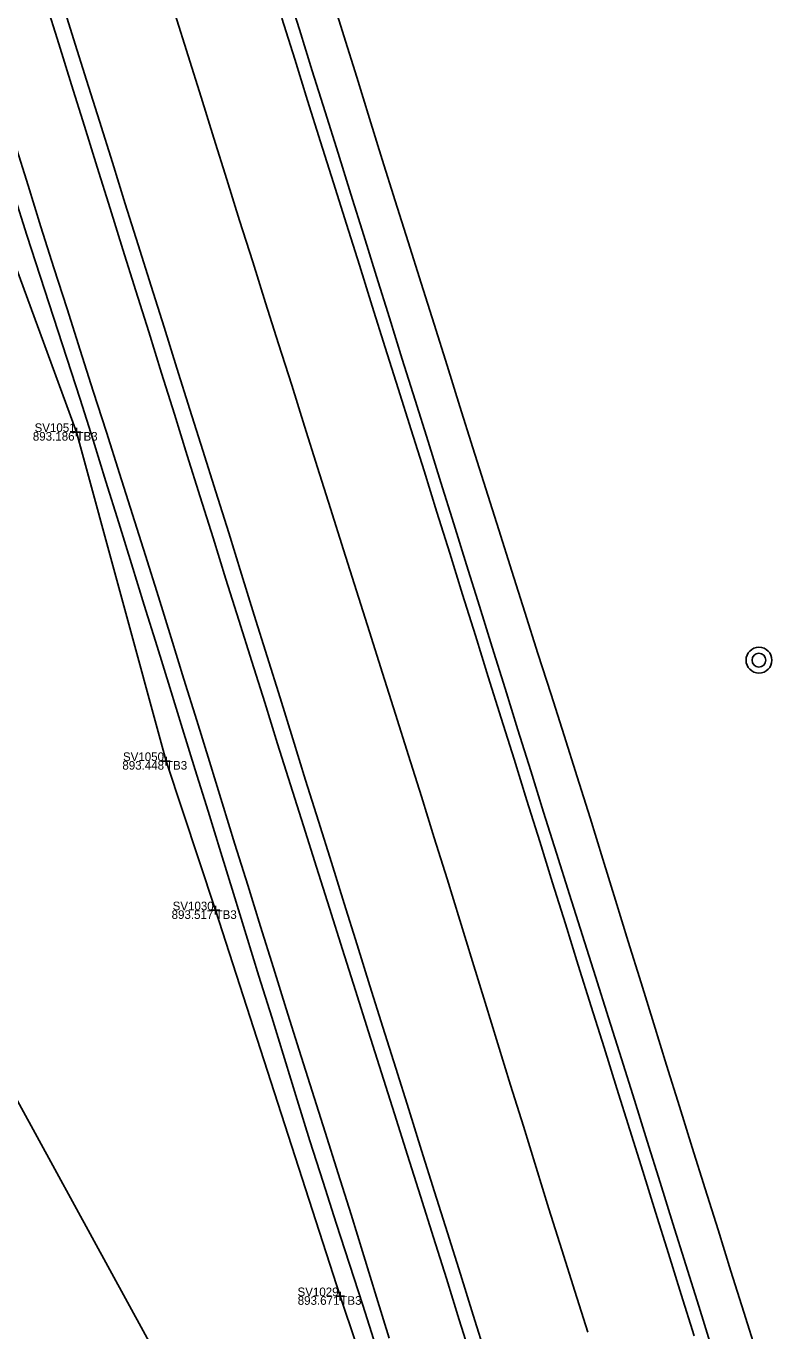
# Model space of a CAD drawing. Extents: x 1918148 to 1919797, y 624701 to 627089.
# Drawn here: x 1919238.3 to 1919324.7, y 625555 to 625706.2 of the extents above; entities that cross this region are included whole.
import ezdxf

# ---------------------------------------------------------------- set-up
doc = ezdxf.new("R2010")
doc.units = 0
for name, color, linetype in [('DR_X_Ditch', 7, 'Continuous'), ('DT_X_Terrain_Boundary', 7, 'Continuous'), ('PM_X_Edge_Line', 7, 'Continuous'), ('PM_X_Lane_Line', 7, 'Continuous'), ('PV_X_EOP', 7, 'Continuous'), ('PV_X_Shoulder_Aggregate', 7, 'Continuous'), ('PV_X_Shoulder_Rumble_Strip', 7, 'Continuous'), ('SV_X_Mon_Cells_Found', 7, 'Continuous'), ('SV_X_Shot_Marker', 7, 'Continuous'), ('SV_X_Text_Comment', 7, 'Continuous'), ('SV_X_Text_Elevation', 7, 'Continuous'), ('SV_X_Text_Name', 7, 'Continuous'), ('SV_X_Top_of_Bank', 7, 'Continuous')]:
    doc.layers.add(name, color=color, linetype=linetype)

msp = doc.modelspace()

# ---------------------------------------------------------------- linework, layer by layer
at = {"layer": 'DR_X_Ditch'}
msp.add_lwpolyline([(1919294.9, 625444.11), (1919278.12, 625494.14), (1919254.13, 625550.83), (1919231.31, 625592.46), (1919223.61, 625606.59), (1919220.8, 625619.65), (1919215.15, 625628.65)], dxfattribs=at)
at = {"layer": 'DT_X_Terrain_Boundary'}
msp.add_lwpolyline([(1919322.98, 625552.38), (1919321.48, 625557.15), (1919319.98, 625561.92), (1919318.49, 625566.69), (1919316.99, 625571.46), (1919315.49, 625576.23), (1919314.01, 625581.01), (1919312.53, 625585.79), (1919311.05, 625590.56), (1919309.57, 625595.34), (1919308.09, 625600.11), (1919306.61, 625604.89), (1919305.13, 625609.67), (1919303.65, 625614.44), (1919302.16, 625619.21), (1919300.64, 625623.98), (1919299.13, 625628.75), (1919297.62, 625633.51), (1919296.11, 625638.28), (1919294.6, 625643.04), (1919293.08, 625647.81), (1919291.57, 625652.58), (1919290.07, 625657.34), (1919288.57, 625662.11), (1919287.07, 625666.88), (1919285.57, 625671.65), (1919284.07, 625676.42), (1919282.57, 625681.19), (1919281.07, 625685.96), (1919279.57, 625690.73), (1919278.08, 625695.5), (1919276.6, 625700.28), (1919275.12, 625705.06), (1919273.64, 625709.83)], dxfattribs=at)
at = {"layer": 'PM_X_Edge_Line'}
for points in [[(1919242.28, 625709.48), (1919243.78, 625704.71), (1919245.27, 625699.94), (1919246.77, 625695.17), (1919248.27, 625690.4), (1919249.76, 625685.62), (1919251.26, 625680.85), (1919252.76, 625676.08), (1919254.26, 625671.31), (1919255.76, 625666.54), (1919257.26, 625661.77), (1919258.76, 625657.01), (1919260.26, 625652.24), (1919261.76, 625647.47), (1919263.24, 625642.69), (1919264.73, 625637.92), (1919266.22, 625633.14), (1919267.71, 625628.37), (1919269.19, 625623.6), (1919270.68, 625618.82), (1919272.17, 625614.05), (1919273.66, 625609.28), (1919275.15, 625604.5), (1919276.65, 625599.73), (1919278.14, 625594.96), (1919279.64, 625590.19), (1919281.14, 625585.42), (1919282.63, 625580.65), (1919284.13, 625575.88), (1919285.63, 625571.11), (1919287.12, 625566.34), (1919288.62, 625561.57), (1919290.11, 625556.8), (1919291.6, 625552.02)], [(1919267.92, 625707.12), (1919269.42, 625702.35), (1919270.91, 625697.57), (1919272.41, 625692.8), (1919273.91, 625688.03), (1919275.41, 625683.26), (1919276.91, 625678.5), (1919278.41, 625673.73), (1919279.91, 625668.96), (1919281.41, 625664.19), (1919282.91, 625659.42), (1919284.42, 625654.65), (1919285.91, 625649.88), (1919287.39, 625645.1), (1919288.88, 625640.33), (1919290.37, 625635.56), (1919291.86, 625630.78), (1919293.35, 625626.01), (1919294.84, 625621.24), (1919296.32, 625616.46), (1919297.82, 625611.69), (1919299.31, 625606.92), (1919300.8, 625602.15), (1919302.29, 625597.37), (1919303.79, 625592.6), (1919305.28, 625587.83), (1919306.77, 625583.06), (1919308.27, 625578.29), (1919309.76, 625573.51), (1919311.25, 625568.74), (1919312.74, 625563.97), (1919314.22, 625559.2), (1919315.71, 625554.42)]]:
    msp.add_lwpolyline(points, dxfattribs=at)
at = {"layer": 'PM_X_Lane_Line'}
msp.add_lwpolyline([(1919255.57, 625707.53), (1919257.06, 625702.75), (1919258.55, 625697.98), (1919260.04, 625693.21), (1919261.53, 625688.44), (1919263.03, 625683.67), (1919264.54, 625678.9), (1919266.04, 625674.13), (1919267.55, 625669.36), (1919269.06, 625664.6), (1919270.56, 625659.83), (1919272.07, 625655.06), (1919273.57, 625650.29), (1919275.08, 625645.52), (1919276.58, 625640.76), (1919278.09, 625635.99), (1919279.59, 625631.22), (1919281.09, 625626.45), (1919282.6, 625621.68), (1919284.1, 625616.91), (1919285.6, 625612.14), (1919287.08, 625607.37), (1919288.56, 625602.59), (1919290.03, 625597.81), (1919291.5, 625593.03), (1919292.98, 625588.26), (1919294.45, 625583.48), (1919295.92, 625578.7), (1919297.4, 625573.92), (1919298.89, 625569.15), (1919300.39, 625564.38), (1919301.89, 625559.61), (1919303.39, 625554.84)], dxfattribs=at)
at = {"layer": 'PV_X_EOP'}
for points in [[(1919273.64, 625709.83), (1919275.12, 625705.06), (1919276.6, 625700.28), (1919278.08, 625695.5), (1919279.57, 625690.73), (1919281.07, 625685.96), (1919282.57, 625681.19), (1919284.07, 625676.42), (1919285.57, 625671.65), (1919287.07, 625666.88), (1919288.57, 625662.11), (1919290.07, 625657.34), (1919291.57, 625652.58), (1919293.08, 625647.81), (1919294.6, 625643.04), (1919296.11, 625638.28), (1919297.62, 625633.51), (1919299.13, 625628.75), (1919300.64, 625623.98), (1919302.16, 625619.21), (1919303.65, 625614.44), (1919305.13, 625609.67), (1919306.61, 625604.89), (1919308.09, 625600.11), (1919309.57, 625595.34), (1919311.05, 625590.56), (1919312.53, 625585.79), (1919314.01, 625581.01), (1919315.49, 625576.23), (1919316.99, 625571.46), (1919318.49, 625566.69), (1919319.98, 625561.92), (1919321.48, 625557.15), (1919322.98, 625552.38)], [(1919280.37, 625554.13), (1919278.9, 625558.91), (1919277.42, 625563.69), (1919275.94, 625568.46), (1919274.44, 625573.23), (1919272.94, 625578), (1919271.44, 625582.77), (1919269.94, 625587.54), (1919268.44, 625592.31), (1919266.95, 625597.08), (1919265.45, 625601.85), (1919263.96, 625606.63), (1919262.48, 625611.4), (1919261, 625616.18), (1919259.53, 625620.96), (1919258.05, 625625.73), (1919256.57, 625630.51), (1919255.1, 625635.29), (1919253.62, 625640.06), (1919252.13, 625644.84), (1919250.61, 625649.6), (1919249.09, 625654.37), (1919247.58, 625659.13), (1919246.06, 625663.89), (1919244.54, 625668.66), (1919243.02, 625673.42), (1919241.5, 625678.18), (1919239.98, 625682.95), (1919238.5, 625687.72), (1919237.02, 625692.5)]]:
    msp.add_lwpolyline(points, dxfattribs=at)
at = {"layer": 'PV_X_Shoulder_Aggregate'}
msp.add_lwpolyline([(1919236.84, 625686.75), (1919238.37, 625681.99), (1919239.91, 625677.23), (1919241.44, 625672.47), (1919242.98, 625667.72), (1919244.52, 625662.96), (1919246.05, 625658.2), (1919247.53, 625653.42), (1919249.01, 625648.65), (1919250.49, 625643.87), (1919251.97, 625639.09), (1919253.45, 625634.32), (1919254.92, 625629.54), (1919256.4, 625624.76), (1919257.88, 625619.99), (1919259.36, 625615.21), (1919260.84, 625610.43), (1919262.31, 625605.66), (1919263.79, 625600.88), (1919265.27, 625596.1), (1919266.75, 625591.33), (1919268.23, 625586.55), (1919269.71, 625581.78), (1919271.18, 625577), (1919272.7, 625572.24), (1919274.23, 625567.48), (1919275.77, 625562.72), (1919277.3, 625557.96), (1919278.83, 625553.2)], dxfattribs=at)
at = {"layer": 'PV_X_Shoulder_Rumble_Strip'}
for points in [[(1919268.45, 625710.57), (1919269.95, 625705.8), (1919271.45, 625701.03), (1919272.94, 625696.26), (1919274.44, 625691.48), (1919275.93, 625686.71), (1919277.42, 625681.94), (1919278.91, 625677.17), (1919280.4, 625672.39), (1919281.89, 625667.62), (1919283.38, 625662.85), (1919284.87, 625658.07), (1919286.36, 625653.3), (1919287.85, 625648.53), (1919289.34, 625643.75), (1919290.83, 625638.98), (1919292.32, 625634.21), (1919293.8, 625629.44), (1919295.29, 625624.66), (1919296.78, 625619.89), (1919298.27, 625615.12), (1919299.78, 625610.35), (1919301.28, 625605.58), (1919302.78, 625600.81), (1919304.28, 625596.04), (1919305.78, 625591.27), (1919307.29, 625586.5), (1919308.79, 625581.73), (1919310.29, 625576.96), (1919311.78, 625572.19), (1919313.27, 625567.42), (1919314.76, 625562.64), (1919316.25, 625557.87), (1919317.73, 625553.1)], [(1919240.56, 625708.93), (1919242.05, 625704.16), (1919243.54, 625699.39), (1919245.03, 625694.61), (1919246.52, 625689.84), (1919248.01, 625685.07), (1919249.5, 625680.3), (1919250.99, 625675.52), (1919252.48, 625670.75), (1919253.97, 625665.98), (1919255.46, 625661.21), (1919256.96, 625656.43), (1919258.45, 625651.66), (1919259.94, 625646.89), (1919261.44, 625642.12), (1919262.93, 625637.35), (1919264.43, 625632.58), (1919265.93, 625627.81), (1919267.43, 625623.04), (1919268.93, 625618.27), (1919270.42, 625613.5), (1919271.92, 625608.73), (1919273.43, 625603.96), (1919274.94, 625599.19), (1919276.45, 625594.43), (1919277.96, 625589.66), (1919279.47, 625584.89), (1919280.99, 625580.13), (1919282.5, 625575.36), (1919284.01, 625570.6), (1919285.51, 625565.83), (1919287, 625561.05), (1919288.49, 625556.28), (1919289.98, 625551.51)]]:
    msp.add_lwpolyline(points, dxfattribs=at)
at = {"layer": 'SV_X_Mon_Cells_Found'}
for radius in [1.5, 0.8]:
    msp.add_circle((1919323.24, 625632.72), radius, dxfattribs=at)
at = {"layer": 'SV_X_Shot_Marker'}
for p, q in [((1919243.61, 625659.16), (1919244.61, 625659.16)), ((1919244.11, 625659.66), (1919244.11, 625658.66)), ((1919244.11, 625659.16), (1919244.11, 625659.16)), ((1919254.49, 625621.53), (1919254.49, 625620.53)), ((1919253.99, 625621.03), (1919254.99, 625621.03)), ((1919254.49, 625621.03), (1919254.49, 625621.03)), ((1919259.74, 625603.73), (1919260.74, 625603.73)), ((1919260.24, 625604.23), (1919260.24, 625603.23)), ((1919260.24, 625603.73), (1919260.24, 625603.73)), ((1919274.7, 625559.51), (1919274.7, 625558.51)), ((1919274.2, 625559.01), (1919275.2, 625559.01)), ((1919274.7, 625559.01), (1919274.7, 625559.01))]:
    msp.add_line(p, q, dxfattribs=at)
at = {"layer": 'SV_X_Top_of_Bank'}
msp.add_lwpolyline([(1919311.1, 625448.91), (1919294.98, 625498.61), (1919274.7, 625559.01), (1919260.24, 625603.73), (1919254.49, 625621.03), (1919244.11, 625659.16), (1919235.03, 625683.79), (1919222.11, 625721.27), (1919200.65, 625791.17)], dxfattribs=at)

# ---------------------------------------------------------------- texts
at = {"layer": 'SV_X_Text_Comment'}
for p in [(1919244.11, 625658.16), (1919254.49, 625620.03), (1919260.24, 625602.73), (1919274.7, 625558.01)]:
    msp.add_text('TB3', height=1, dxfattribs=at).set_placement(p)
at = {"layer": 'SV_X_Text_Elevation'}
for s, p in [('893.186', (1919239.05, 625658.16)), ('893.448', (1919249.43, 625620.03)), ('893.517', (1919255.14, 625602.73)), ('893.671', (1919269.76, 625558.01))]:
    msp.add_text(s, height=1, dxfattribs=at).set_placement(p)
at = {"layer": 'SV_X_Text_Name'}
for s, p in [('SV1051', (1919239.25, 625659.16)), ('SV1050', (1919249.5, 625621.03)), ('SV1030', (1919255.26, 625603.73)), ('SV1029', (1919269.74, 625559.01))]:
    msp.add_text(s, height=1, dxfattribs=at).set_placement(p)

doc.saveas('drawing.dxf')
